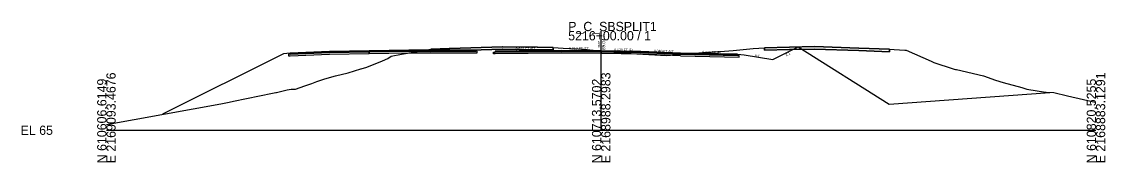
# Model space of a CAD drawing. Extents: x -26 to 1303, y -3010 to 12033.
# Drawn here: x 974.3 to 1302.8, y 9990.3 to 10032.8 of the extents above; entities that cross this region are included whole.
import ezdxf

# ---------------------------------------------------------------- set-up
doc = ezdxf.new("R2010")
doc.units = 0
for name, color, linetype in [('RD_GPK_XS_Cell', 7, 'Continuous'), ('RD_Sketch10', 7, 'Continuous'), ('RD_XS_Base', 7, 'Continuous'), ('RD_XS_ExGround', 7, 'Continuous'), ('RD_XS_ExPaveRet', 7, 'Continuous'), ('RD_XS_Greenside', 7, 'Continuous'), ('RD_XS_Pave', 7, 'Continuous'), ('RD_XS_PaveOvlay_CP', 7, 'Continuous'), ('RD_XS_TieSlope', 7, 'Continuous'), ('RD_XS_TX_Elev_EX', 7, 'Continuous'), ('RD_XS_TX_Elev_PR', 7, 'Continuous'), ('RD_XS_TX_Slope', 7, 'Continuous')]:
    doc.layers.add(name, color=color, linetype=linetype)

msp = doc.modelspace()

# ---------------------------------------------------------------- linework, layer by layer
at = {"layer": 'RD_GPK_XS_Cell'}
for p, q in [((1150, 10000), (1150, 10030)), ((1000, 10000), (1150, 10000)), ((1150, 10000), (1300, 10000))]:
    msp.add_line(p, q, dxfattribs=at)
at = {"layer": 'RD_Sketch10'}
msp.add_lwpolyline([(1209.69, 10025.2), (1237.27, 10007.88), (1286.04, 10011.45)], dxfattribs=at)
at = {"layer": 'RD_XS_Base'}
for p, q in [((1079.67, 10023.73), (1067.67, 10023.49)), ((1079.67, 10023.73), (1079.67, 10023.88)), ((1079.67, 10023.88), (1079.67, 10023.23)), ((1091.67, 10023.88), (1079.67, 10023.73)), ((1079.67, 10023.73), (1079.67, 10023.88)), ((1079.67, 10023.88), (1079.67, 10023.88)), ((1079.67, 10023.88), (1079.67, 10023.23)), ((1079.67, 10023.23), (1079.67, 10023.73)), ((1079.67, 10023.73), (1079.67, 10023.73)), ((1079.67, 10023.73), (1079.67, 10023.73)), ((1079.67, 10023.23), (1079.67, 10023.73)), ((1079.67, 10023.73), (1079.67, 10023.73)), ((1112.45, 10023.88), (1091.68, 10023.88)), ((1093.67, 10023.8), (1093.67, 10023.8)), ((1093.67, 10023.8), (1093.67, 10023.8)), ((1111.95, 10023.88), (1111.95, 10023.88)), ((1112.45, 10023.38), (1112.45, 10023.88)), ((1112.45, 10023.86), (1112.45, 10023.86)), ((1117.35, 10023.64), (1117.84, 10023.65)), ((1117.35, 10023.14), (1117.35, 10023.64)), ((1117.35, 10023.63), (1117.35, 10023.63)), ((1117.84, 10023.65), (1137.99, 10023.85)), ((1117.85, 10023.65), (1117.85, 10023.65)), ((1138, 10023.85), (1150, 10023.73)), ((1150, 10023.23), (1150, 10023.88)), ((1150, 10023.88), (1150, 10023.88)), ((1150, 10023.88), (1150, 10023.88)), ((1150, 10023.88), (1150, 10023.73)), ((1150, 10023.73), (1150, 10023.73)), ((1150, 10023.73), (1150, 10023.23)), ((1150, 10023.73), (1150, 10023.73)), ((1150, 10023.73), (1162, 10023.49)), ((1150, 10023.73), (1150, 10023.73)), ((1055.67, 10023.01), (1055.17, 10022.99)), ((1055.17, 10022.99), (1055.17, 10022.99)), ((1055.17, 10022.99), (1055.17, 10022.49)), ((1055.17, 10022.49), (1055.67, 10022.51)), ((1055.17, 10022.49), (1055.17, 10022.49)), ((1055.17, 10022.49), (1055.17, 10022.49)), ((1067.67, 10023.49), (1055.67, 10023.01)), ((1055.67, 10023.01), (1055.67, 10023.01)), ((1055.67, 10022.51), (1067.67, 10022.99)), ((1055.67, 10022.51), (1055.67, 10022.51)), ((1067.67, 10023.49), (1067.67, 10023.49)), ((1067.67, 10022.99), (1079.67, 10023.23)), ((1067.67, 10022.99), (1067.67, 10022.99)), ((1079.67, 10023.23), (1091.67, 10023.38)), ((1079.67, 10023.23), (1079.67, 10023.23)), ((1079.67, 10023.23), (1079.67, 10023.23)), ((1079.67, 10023.23), (1079.67, 10023.23)), ((1079.67, 10023.23), (1079.67, 10023.23)), ((1091.7, 10023.38), (1112.45, 10023.38)), ((1093.67, 10023.3), (1093.67, 10023.3)), ((1093.67, 10023.3), (1093.67, 10023.3)), ((1117.82, 10023.15), (1117.35, 10023.14)), ((1137.98, 10023.35), (1117.82, 10023.15)), ((1117.85, 10023.15), (1117.85, 10023.15)), ((1150, 10023.23), (1138, 10023.35)), ((1162, 10022.99), (1150, 10023.23)), ((1150, 10023.23), (1150, 10023.23)), ((1162, 10023.49), (1162, 10023.49)), ((1162, 10023.49), (1174, 10023.01)), ((1174, 10022.51), (1162, 10022.99)), ((1162, 10022.99), (1162, 10022.99)), ((1191.3, 10022.66), (1174, 10023.01)), ((1174, 10023.01), (1174, 10023.01)), ((1174, 10022.51), (1174, 10022.51)), ((1174, 10022.51), (1191.8, 10022.15)), ((1191.8, 10022.65), (1191.3, 10022.66)), ((1191.3, 10022.66), (1191.3, 10022.66)), ((1191.8, 10022.15), (1191.8, 10022.65)), ((1191.8, 10022.65), (1191.8, 10022.65)), ((1191.8, 10022.15), (1191.8, 10022.15)), ((1191.8, 10022.15), (1191.8, 10022.15))]:
    msp.add_line(p, q, dxfattribs=at)
at = {"layer": 'RD_XS_ExGround'}
msp.add_lwpolyline([(1000, 10001.78), (1034.69, 10008.02), (1037.18, 10008.47), (1038.57, 10008.84), (1050.38, 10011.21), (1051.35, 10011.42), (1051.42, 10011.43), (1051.61, 10011.47), (1054.82, 10012.24), (1056.04, 10012.46), (1057.33, 10012.46), (1060.13, 10013.46), (1062.24, 10014.15), (1063.8, 10014.78), (1066.25, 10015.56), (1069.44, 10016.47), (1073.3, 10017.35), (1077.12, 10018.55), (1077.26, 10018.62), (1078.94, 10019.07), (1083.68, 10020.96), (1085.32, 10021.67), (1086.37, 10022.46), (1089.48, 10023.05), (1098.31, 10024.56), (1103.88, 10024.75), (1119.97, 10025.26), (1130.61, 10025.13), (1135.45, 10025.07), (1138.45, 10024.87), (1143.01, 10024.6), (1144.07, 10024.49), (1144.61, 10024.5), (1150.48, 10023.94), (1154.94, 10023.5), (1157.25, 10023.37), (1169.85, 10022.66), (1177.19, 10023.23), (1180.83, 10023.51), (1182, 10023.54), (1189.99, 10024.15), (1196.11, 10024.77), (1199.52, 10024.98), (1207.08, 10025.14), (1214.67, 10025.31), (1228.15, 10024.84), (1237.44, 10024.52), (1238.83, 10024.46), (1242.07, 10024.27), (1242.5, 10024.25), (1250.03, 10020.87), (1250.8, 10020.53), (1250.83, 10020.52), (1256.75, 10018.59), (1257.04, 10018.5), (1257.39, 10018.42), (1257.67, 10018.37), (1265.86, 10016.5), (1269.57, 10015.2), (1271.85, 10014.48), (1277.53, 10012.92), (1279.04, 10012.48), (1284.71, 10011.52), (1284.88, 10011.5), (1287.2, 10011.4), (1291.4, 10010.46), (1299.71, 10008.47), (1300, 10008.47)], dxfattribs=at)
at = {"layer": 'RD_XS_ExPaveRet'}
for points in [[(1130.67, 10025.13), (1135.45, 10025.07), (1135.45, 10025.06), (1135.45, 10024.32), (1130.67, 10024.38), (1130.61, 10024.38), (1120.11, 10024.51), (1119.97, 10024.51), (1104.09, 10024), (1103.88, 10024), (1098.38, 10023.82), (1098.31, 10023.81), (1098.31, 10023.81), (1098.31, 10023.81), (1098.31, 10024.55), (1098.31, 10024.56), (1098.31, 10024.56), (1098.31, 10024.56), (1098.38, 10024.57), (1103.88, 10024.75), (1104.09, 10024.75), (1119.97, 10025.26), (1120.11, 10025.26), (1130.61, 10025.13), (1130.67, 10025.13)], [(1130.61, 10025.13), (1120.11, 10025.26), (1119.97, 10025.26), (1104.09, 10024.75), (1103.88, 10024.75), (1098.38, 10024.57), (1098.31, 10024.56), (1098.31, 10024.56), (1098.31, 10024.55), (1098.31, 10023.81), (1098.31, 10023.81), (1098.38, 10023.82), (1103.88, 10024), (1104.09, 10024), (1119.97, 10024.51), (1120.11, 10024.51), (1130.61, 10024.38), (1130.67, 10024.38), (1135.45, 10024.32), (1135.45, 10025.06), (1135.45, 10025.07), (1130.67, 10025.13), (1130.61, 10025.13)], [(1237.44, 10024.52), (1237.44, 10024.52), (1237.44, 10023.77), (1237.44, 10023.77), (1237.44, 10023.77), (1228.15, 10024.09), (1228.15, 10024.09), (1214.67, 10024.56), (1207.08, 10024.39), (1207.08, 10024.39), (1199.53, 10024.23), (1199.53, 10024.23), (1199.53, 10024.23), (1199.53, 10024.98), (1199.53, 10024.98), (1207.08, 10025.14), (1207.08, 10025.14), (1214.67, 10025.31), (1228.15, 10024.84), (1228.15, 10024.84), (1237.44, 10024.52)], [(1228.15, 10024.84), (1214.67, 10025.31), (1207.08, 10025.14), (1199.53, 10024.98), (1199.53, 10024.23), (1207.08, 10024.39), (1214.67, 10024.56), (1228.15, 10024.09), (1237.44, 10023.77), (1237.44, 10024.52), (1228.15, 10024.84)]]:
    msp.add_lwpolyline(points, dxfattribs=at)
at = {"layer": 'RD_XS_Greenside'}
for p, q in [((1202.03, 10021.36), (1209.69, 10025.2)), ((1053.67, 10023.16), (1017.03, 10004.84)), ((1193.3, 10022.82), (1202.03, 10021.36))]:
    msp.add_line(p, q, dxfattribs=at)
at = {"layer": 'RD_XS_Pave'}
for p, q in [((1067.67, 10023.8), (1055.67, 10023.32)), ((1067.67, 10023.64), (1055.67, 10023.16)), ((1055.67, 10023.16), (1067.67, 10023.64)), ((1079.67, 10024.04), (1067.67, 10023.8)), ((1079.67, 10023.88), (1067.67, 10023.64)), ((1067.67, 10023.64), (1079.67, 10023.88)), ((1067.67, 10023.8), (1067.67, 10023.8)), ((1067.67, 10023.49), (1079.67, 10023.73)), ((1067.67, 10023.64), (1067.67, 10023.64)), ((1067.67, 10023.64), (1067.67, 10023.64)), ((1091.67, 10024.19), (1079.67, 10024.04)), ((1079.67, 10024.04), (1079.67, 10024.04)), ((1091.67, 10024.03), (1079.67, 10023.88)), ((1079.67, 10023.88), (1091.67, 10024.03)), ((1079.67, 10023.73), (1079.67, 10023.88)), ((1079.67, 10023.88), (1079.67, 10023.73)), ((1079.67, 10023.88), (1079.67, 10023.88)), ((1079.67, 10023.88), (1079.67, 10023.73)), ((1079.67, 10023.73), (1091.67, 10023.88)), ((1079.67, 10023.73), (1079.67, 10023.88)), ((1079.67, 10023.88), (1079.67, 10023.88)), ((1079.67, 10023.88), (1079.67, 10023.88)), ((1079.67, 10023.73), (1079.67, 10023.73)), ((1079.67, 10023.73), (1079.67, 10023.73)), ((1079.67, 10023.73), (1079.67, 10023.73)), ((1079.67, 10023.73), (1079.67, 10023.73)), ((1111.95, 10024.19), (1091.67, 10024.19)), ((1111.95, 10024.03), (1091.67, 10024.03)), ((1091.67, 10024.03), (1111.95, 10024.03)), ((1091.68, 10023.88), (1111.96, 10023.88)), ((1093.67, 10024.11), (1093.67, 10024.11)), ((1093.67, 10024.11), (1093.67, 10024.11)), ((1093.67, 10023.95), (1093.67, 10023.95)), ((1093.67, 10023.95), (1093.67, 10023.95)), ((1093.67, 10023.95), (1093.67, 10023.95)), ((1093.67, 10023.95), (1093.67, 10023.95)), ((1093.67, 10023.8), (1093.67, 10023.8)), ((1093.67, 10023.8), (1093.67, 10023.8)), ((1111.95, 10024.03), (1111.95, 10024.19)), ((1111.95, 10024.19), (1111.95, 10024.19)), ((1111.95, 10023.88), (1111.95, 10024.03)), ((1111.95, 10024.03), (1111.95, 10024.03)), ((1138, 10024.01), (1117.84, 10023.81)), ((1117.84, 10023.81), (1138, 10024.01)), ((1117.84, 10023.65), (1137.99, 10023.85)), ((1138, 10024.17), (1117.85, 10023.96)), ((1117.85, 10023.96), (1117.85, 10023.96)), ((1117.85, 10023.96), (1117.85, 10023.81)), ((1117.85, 10023.81), (1117.85, 10023.81)), ((1117.85, 10023.81), (1117.85, 10023.65)), ((1150, 10024.04), (1138, 10024.17)), ((1150, 10023.88), (1138, 10024.01)), ((1138, 10024.01), (1150, 10023.88)), ((1138, 10023.85), (1150, 10023.73)), ((1162, 10023.8), (1150, 10024.04)), ((1150, 10024.04), (1150, 10024.04)), ((1150, 10023.73), (1150, 10023.88)), ((1150, 10023.88), (1150, 10023.88)), ((1150, 10023.88), (1150, 10023.88)), ((1150, 10023.88), (1162, 10023.64)), ((1162, 10023.64), (1150, 10023.88)), ((1150, 10023.88), (1150, 10023.88)), ((1150, 10023.88), (1150, 10023.88)), ((1150, 10023.88), (1150, 10023.88)), ((1150, 10023.88), (1150, 10023.73)), ((1150, 10023.73), (1150, 10023.73)), ((1150, 10023.73), (1150, 10023.73)), ((1150, 10023.73), (1162, 10023.49)), ((1174, 10023.32), (1162, 10023.8)), ((1162, 10023.8), (1162, 10023.8)), ((1162, 10023.64), (1162, 10023.64)), ((1162, 10023.64), (1174, 10023.16)), ((1174, 10023.16), (1162, 10023.64)), ((1162, 10023.64), (1162, 10023.64)), ((1055.67, 10023.01), (1067.67, 10023.49)), ((1055.67, 10023.32), (1055.67, 10023.32)), ((1055.67, 10023.32), (1055.67, 10023.16)), ((1055.67, 10023.16), (1055.67, 10023.16)), ((1055.67, 10023.16), (1055.67, 10023.01)), ((1055.67, 10023.16), (1055.67, 10023.16)), ((1055.67, 10023.16), (1055.67, 10023.16)), ((1055.67, 10023.01), (1055.67, 10023.01)), ((1055.67, 10023.01), (1055.67, 10023.01)), ((1067.67, 10023.49), (1067.67, 10023.49)), ((1162, 10023.49), (1174, 10023.01)), ((1162, 10023.49), (1162, 10023.49)), ((1191.3, 10022.98), (1174, 10023.32)), ((1174, 10023.32), (1174, 10023.32)), ((1174, 10023.16), (1174, 10023.16)), ((1174, 10023.16), (1191.3, 10022.82)), ((1191.3, 10022.82), (1174, 10023.16)), ((1174, 10023.16), (1174, 10023.16)), ((1174, 10023.01), (1174, 10023.01)), ((1174, 10023.01), (1191.3, 10022.66)), ((1191.3, 10022.82), (1191.3, 10022.98)), ((1191.3, 10022.98), (1191.3, 10022.98)), ((1191.3, 10022.82), (1191.3, 10022.82)), ((1191.3, 10022.82), (1191.3, 10022.82)), ((1191.3, 10022.66), (1191.3, 10022.82)), ((1191.3, 10022.82), (1191.3, 10022.82)), ((1191.3, 10022.66), (1191.3, 10022.66)), ((1191.3, 10022.66), (1191.3, 10022.66))]:
    msp.add_line(p, q, dxfattribs=at)
at = {"layer": 'RD_XS_PaveOvlay_CP'}
for p, q in [((1055.67, 10023.32), (1067.67, 10023.8)), ((1067.67, 10023.8), (1079.67, 10024.04)), ((1091.67, 10024.19), (1079.67, 10024.04)), ((1079.67, 10024.04), (1079.67, 10024.04)), ((1111.95, 10024.19), (1091.67, 10024.19)), ((1093.67, 10024.11), (1093.67, 10024.11)), ((1093.67, 10024.11), (1093.67, 10024.11)), ((1138, 10024.17), (1117.85, 10023.96)), ((1150, 10024.04), (1138, 10024.17)), ((1162, 10023.8), (1150, 10024.04)), ((1150, 10024.04), (1150, 10024.04)), ((1174, 10023.32), (1162, 10023.8)), ((1162, 10023.8), (1162, 10023.8)), ((1191.3, 10022.98), (1174, 10023.32)), ((1174, 10023.32), (1174, 10023.32)), ((1191.3, 10022.98), (1191.3, 10022.98))]:
    msp.add_line(p, q, dxfattribs=at)
at = {"layer": 'RD_XS_TieSlope'}
for p, q in [((1055.67, 10023.32), (1053.67, 10023.16)), ((1191.3, 10022.98), (1193.3, 10022.82))]:
    msp.add_line(p, q, dxfattribs=at)

# ---------------------------------------------------------------- texts
at = {"layer": 'RD_GPK_XS_Cell'}
for s, p in [('5216+00.00 / 1', (1140, 10027.2)), ('P_C_SBSPLIT1', (1140, 10030)), ('EL 65', (974, 9998.6))]:
    msp.add_text(s, height=2.8, dxfattribs=at).set_placement(p)
for s, p in [('E 2169093.4676', (1002.8, 9990)), ('E 2168988.2983', (1152.8, 9990)), ('E 2168883.1291', (1302.8, 9990)), ('N 610606.6149', (1000, 9990)), ('N 610713.5702', (1150, 9990)), ('N 610820.5255', (1300, 9990))]:
    msp.add_text(s, height=2.8, rotation=90, dxfattribs=at).set_placement(p)
at = {"layer": 'RD_XS_TX_Elev_EX'}
msp.add_text('88.97', height=0.6, rotation=90, dxfattribs=at).set_placement((1149.63, 10025))
at = {"layer": 'RD_XS_TX_Elev_PR'}
msp.add_text('89.04', height=1, rotation=90, dxfattribs=at).set_placement((1151.22, 10024.29))
at = {"layer": 'RD_XS_TX_Slope'}
for s, rotation, p in [('0.010 FT./FT.', 0.5729, (1124.06, 10024.21)), ('0.013 FT./FT.', 359.2836, (1140.27, 10024.4)), ('0.020 FT./FT.', 358.8542, (1153.94, 10023.99)), ('0.040 FT./FT.', 357.7094, (1165.94, 10023.67)), ('0.020 FT./FT.', 358.8542, (1180.59, 10023.29)), ('2:1', 26.5651, (1206.13, 10022.36)), ('6:1', 350.5377, (1196.6, 10022.32))]:
    msp.add_text(s, height=0.75, rotation=rotation, dxfattribs=at).set_placement(p)

doc.saveas('drawing.dxf')
